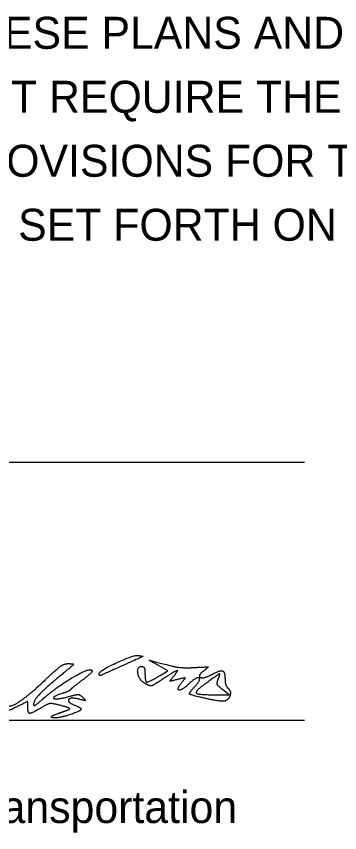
# Model space of a CAD drawing. Extents: x -31.7 to 34, y 0 to 22.
# Drawn here: x 26.767 to 28.181, y 7.305 to 10.877 of the extents above; entities that cross this region are included whole.
import ezdxf

# ---------------------------------------------------------------- set-up
doc = ezdxf.new("R2010")
doc.units = 0
doc.layers.add('SH_Data', color=7, linetype='Continuous')
doc.layers.add('SH_Text', color=7, linetype='Continuous')

msp = doc.modelspace()

# ---------------------------------------------------------------- linework, layer by layer
at = {"layer": 'SH_Data'}
for p, q in [((24.5279, 8.9262), (28.0279, 8.9262)), ((24.5279, 7.7968), (28.0279, 7.7968))]:
    msp.add_line(p, q, dxfattribs=at)
at = {"layer": 'SH_Text'}
for p, q in [((27.1295, 8.001), (27.1295, 8.001)), ((27.582, 7.8948), (27.582, 7.8948))]:
    msp.add_line(p, q, dxfattribs=at)
for points in [[(27.3933, 7.9914), (27.4297, 8.0129), (27.3889, 8.0359)], [(27.642, 7.9079), (27.6982, 7.908), (27.6695, 7.9301)]]:
    msp.add_lwpolyline(points, dxfattribs=at)
for points in [[(27.1295, 8.001), (27.1295, 8.0134), (27.2823, 8.0837), (27.3012, 8.08)], [(27.3012, 8.08), (27.3219, 8.076), (27.3226, 8.0764), (27.201, 8.0218)], [(26.8951, 7.9753), (26.9403, 8.019), (26.9774, 8.0447), (26.9951, 8.0444)], [(26.9951, 8.0444), (27.0194, 8.0439), (27.0156, 8.0375), (26.967, 7.9975)], [(27.3889, 8.0359), (27.3461, 8.06), (27.3452, 8.06), (27.4482, 8.0336)], [(26.8763, 7.8841), (26.93, 7.9329), (27.0769, 8.0229), (27.0938, 8.0172)], [(27.0938, 8.0172), (27.1022, 8.0144), (27.087, 7.9957), (27.0599, 7.9755)], [(27.201, 8.0218), (27.1385, 7.9937), (27.1295, 7.9911), (27.1295, 8.001)], [(27.3305, 7.9569), (27.304, 7.9711), (27.293, 8.0324), (27.317, 8.0324)], [(27.317, 8.0324), (27.3238, 8.0324), (27.3295, 8.0184), (27.3295, 8.0012)], [(27.4529, 7.9866), (27.4773, 8.0162), (27.4615, 8.0124), (27.4052, 7.9752)], [(27.4482, 8.0336), (27.4688, 8.0284), (27.5138, 8.0256), (27.5482, 8.0275)], [(27.5482, 8.0275), (27.6031, 8.0306), (27.608, 8.029), (27.5881, 8.0142)], [(27.5881, 8.0142), (27.5593, 7.9927), (27.5822, 7.9763), (27.6159, 7.9944)], [(27.6159, 7.9944), (27.6561, 8.0159), (27.6795, 8.0101), (27.6795, 7.9787)], [(26.7295, 7.8684), (26.7295, 7.8456), (26.8248, 7.907), (26.8951, 7.9753)], [(26.967, 7.9975), (26.8929, 7.9366), (26.842, 7.883), (26.842, 7.8663)], [(27.0599, 7.9755), (27.0328, 7.9553), (27.0079, 7.9353), (27.0045, 7.9311)], [(27.3295, 8.0012), (27.3295, 7.9644), (27.3438, 7.9622), (27.3933, 7.9914)], [(27.4052, 7.9752), (27.3652, 7.9487), (27.3519, 7.9454), (27.3305, 7.9569)], [(27.4723, 7.9749), (27.4392, 7.9667), (27.4374, 7.9678), (27.4529, 7.9866)], [(27.4924, 7.9642), (27.507, 7.9818), (27.5047, 7.983), (27.4723, 7.9749)], [(27.5462, 7.9428), (27.5767, 7.9764), (27.5551, 7.9874), (27.5211, 7.9554)], [(27.6497, 7.9756), (27.6596, 8.0014), (27.6514, 7.9983), (27.5888, 7.9527)], [(27.6695, 7.9301), (27.6491, 7.9458), (27.6434, 7.959), (27.6497, 7.9756)], [(27.6795, 7.9787), (27.6795, 7.9629), (27.6858, 7.9436), (27.6936, 7.9358)], [(27.0045, 7.9311), (27.001, 7.9268), (26.9856, 7.9194), (26.9701, 7.9145)], [(27.5211, 7.9554), (27.4892, 7.9255), (27.4661, 7.9325), (27.4924, 7.9642)], [(27.582, 7.8948), (27.5272, 7.9077), (27.5215, 7.9154), (27.5462, 7.9428)], [(27.5888, 7.9527), (27.5461, 7.9217), (27.5626, 7.9078), (27.642, 7.9079)], [(27.6936, 7.9358), (27.7014, 7.928), (27.7044, 7.9128), (27.7003, 7.902)], [(26.9701, 7.9145), (26.9206, 7.8991), (26.9401, 7.8854), (26.9919, 7.8992)], [(26.9919, 7.8992), (27.0302, 7.9095), (27.0455, 7.9089), (27.0575, 7.8966)], [(27.0575, 7.8966), (27.0702, 7.8837), (27.0666, 7.8823), (27.0388, 7.8892)], [(27.7003, 7.902), (27.6922, 7.8809), (27.651, 7.8784), (27.582, 7.8948)], [(26.817, 7.8559), (26.817, 7.8788), (26.8159, 7.8788), (26.7698, 7.8559)], [(26.842, 7.8663), (26.842, 7.8588), (26.8574, 7.8668), (26.8763, 7.8841)], [(26.9621, 7.8609), (26.9233, 7.8708), (26.9065, 7.8691), (26.8789, 7.8528)], [(26.992, 7.8417), (27.0034, 7.8458), (26.9917, 7.8533), (26.9621, 7.8609)], [(27.0388, 7.8892), (27.0021, 7.8982), (26.9889, 7.8751), (27.0232, 7.862)], [(27.0232, 7.862), (27.0538, 7.8502), (27.0449, 7.8353), (26.9981, 7.8199)], [(26.7698, 7.8559), (26.7324, 7.8374), (26.7138, 7.8351), (26.6807, 7.8446)], [(26.8789, 7.8528), (26.8339, 7.8262), (26.817, 7.8271), (26.817, 7.8559)], [(26.9981, 7.8199), (26.9515, 7.8045), (26.9042, 7.8102), (26.9482, 7.8259)], [(26.9482, 7.8259), (26.962, 7.8308), (26.9817, 7.8379), (26.992, 7.8417)]]:
    msp.add_open_spline(points, degree=2, dxfattribs=at)

# ---------------------------------------------------------------- texts
at = {"layer": 'SH_Data'}
for s, p in [(' I HEREBY APPROVE THESE PLANS AND DECLARE THAT THE MAKING OF THIS', (24.5279, 10.735)), ('IMPROVEMENT WILL NOT REQUIRE THE CLOSING TO TRAFFIC OF THE', (24.5279, 10.455)), ('HIGHWAY AND THAT PROVISIONS FOR THE MAINTENANCE AND SAFETY', (24.5279, 10.175)), ('OF TRAFFIC WILL BE AS SET FORTH ON THE PLANS AND ESTIMATES.', (24.5279, 9.895))]:
    msp.add_text(s, height=0.14, dxfattribs=at).set_placement(p)
at = {"layer": 'SH_Text'}
msp.add_text('Director, Department of Transportation', height=0.14, dxfattribs=at).set_placement((24.5279, 7.3468))

doc.saveas('drawing.dxf')
